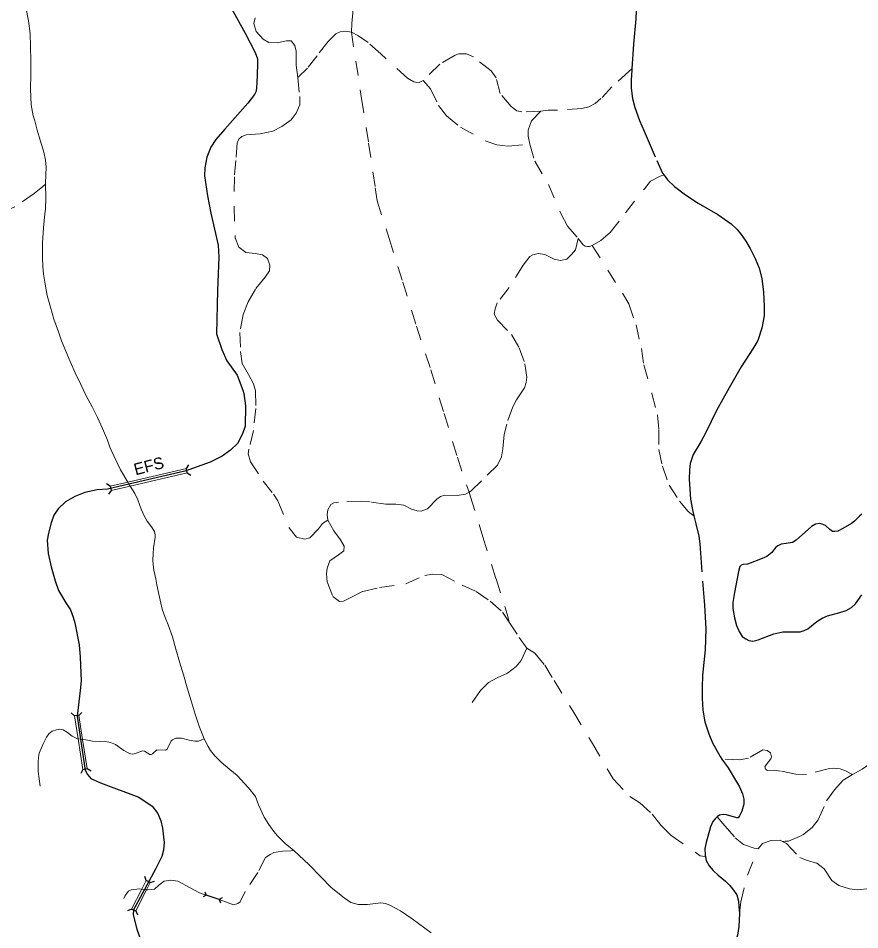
# Model space of a CAD drawing. Extents: x 703.1 to 728.9, y 7316.2 to 7344.3.
# Drawn here: x 708.41 to 714.18, y 7332.5 to 7338.75 of the extents above; entities that cross this region are included whole.
import ezdxf
from ezdxf.enums import TextEntityAlignment as Align

# ---------------------------------------------------------------- set-up
doc = ezdxf.new("R2010")
doc.units = 0
doc.header["$LTSCALE"] = 0.032
for name, pattern in [('DOTTED', [1.5, 0.3, -1.2]), ('LONG_DASHED', [7.5, 6, -1.5]), ('MEDIUM_DASHED', [4.5, 3, -1.5])]:
    doc.linetypes.add(name, pattern=pattern)
for name, color, linetype, lineweight in [('15', 7, 'Continuous', 25), ('29', 7, 'Continuous', 25), ('30', 7, 'Continuous', 13), ('31', 7, 'Continuous', 25), ('4', 7, 'LONG_DASHED', 25), ('5', 7, 'LONG_DASHED', 13), ('6', 7, 'MEDIUM_DASHED', 13), ('7', 7, 'DOTTED', 13)]:
    doc.layers.add(name, color=color, linetype=linetype, lineweight=lineweight)
doc.layers.add('61', color=7, linetype='Continuous')

msp = doc.modelspace()

# ---------------------------------------------------------------- linework, layer by layer
at = {"layer": '15'}
for points in [[(709.8722, 7338.8202), (709.9672, 7338.652), (710.0352, 7338.5185), (710.0515, 7338.4757), (710.0509, 7338.4335), (710.0459, 7338.3088), (710.0421, 7338.2534), (710.0308, 7338.2319), (709.9842, 7338.1715), (709.8274, 7337.9932), (709.7645, 7337.9227), (709.7305, 7337.8698), (709.7034, 7337.8012), (709.6895, 7337.7282), (709.687, 7337.6727), (709.7072, 7337.5355), (709.7317, 7337.4177), (709.7808, 7337.1973), (709.7864, 7337.1148), (709.7763, 7336.8868), (709.7707, 7336.5901), (709.8065, 7336.4825), (709.8418, 7336.4031)], [(709.8418, 7336.4031), (709.911, 7336.3061), (709.9507, 7336.2035), (709.957, 7336.1796), (709.9683, 7336.0952), (709.9658, 7335.9566), (709.9489, 7335.9044)], [(709.9489, 7335.9044), (709.9149, 7335.8364), (709.8658, 7335.7923), (709.8091, 7335.7495), (709.7254, 7335.7086), (709.5793, 7335.6557), (709.5535, 7335.6463), (709.1697, 7335.558)], [(709.1697, 7335.558), (709.0222, 7335.5241), (708.9517, 7335.5191), (708.8674, 7335.5002), (708.7987, 7335.4731), (708.7333, 7335.4378), (708.6842, 7335.3899), (708.654, 7335.3446), (708.6351, 7335.293), (708.6187, 7335.2212), (708.6086, 7335.1733), (708.6156, 7335.082), (708.6357, 7334.9901), (708.6634, 7334.8944), (708.6873, 7334.8289), (708.7371, 7334.7438), (708.7685, 7334.6972), (708.7874, 7334.6469), (708.7988, 7334.6066), (708.8277, 7334.4567), (708.8359, 7334.3716), (708.841, 7334.2092), (708.834, 7334.143), (708.8139, 7333.9667), (708.8377, 7333.8096)], [(708.8377, 7333.8096), (708.8699, 7333.5971), (708.8843, 7333.5662), (708.9082, 7333.5397), (708.9737, 7333.5095), (709.2381, 7333.4125), (709.3287, 7333.3508), (709.3677, 7333.2992), (709.3879, 7333.2501), (709.3986, 7333.199), (709.4111, 7333.1008), (709.4061, 7333.0479), (709.3948, 7333.0038), (709.3545, 7332.922), (709.277, 7332.7781)], [(709.277, 7332.7781), (709.2015, 7332.6379), (709.1977, 7332.6052), (709.2236, 7332.505), (709.2701, 7332.3753), (709.3092, 7332.2997), (709.4206, 7332.1555), (709.4634, 7332.0838), (709.5024, 7331.9943), (709.5188, 7331.9238), (709.5244, 7331.8261), (709.5194, 7331.714), (709.5043, 7331.6183), (709.481, 7331.5233), (709.4457, 7331.4439), (709.3991, 7331.3608), (709.3035, 7331.2512), (709.2575, 7331.1965), (709.1933, 7331.102), (709.1606, 7331.034), (709.1445, 7330.9905)]]:
    msp.add_lwpolyline(points, dxfattribs=at)
at = {"layer": '29'}
for p, q in [((709.5636, 7335.666), (709.5805, 7335.6906)), ((709.5691, 7335.636), (709.5636, 7335.666)), ((709.5691, 7335.636), (709.5939, 7335.6189)), ((709.0406, 7335.5439), (709.0157, 7335.5608)), ((709.0406, 7335.5439), (709.0464, 7335.514)), ((709.0464, 7335.514), (709.0297, 7335.4893)), ((708.7951, 7333.9695), (708.773, 7333.9895)), ((708.8255, 7333.9709), (708.7951, 7333.9695)), ((708.8255, 7333.9709), (708.8458, 7333.9932)), ((708.8541, 7333.6003), (708.8388, 7333.5744)), ((708.8541, 7333.6003), (708.8837, 7333.6079)), ((708.8837, 7333.6079), (708.9093, 7333.5928)), ((709.2884, 7332.84), (709.2788, 7332.8681)), ((709.3158, 7332.8265), (709.2884, 7332.84)), ((709.3158, 7332.8265), (709.3443, 7332.8361)), ((709.1873, 7332.6434), (709.1598, 7332.6314)), ((709.1873, 7332.6434), (709.2158, 7332.6323)), ((709.2158, 7332.6323), (709.2278, 7332.6051))]:
    msp.add_line(p, q, dxfattribs=at)
at = {"layer": '30'}
for points in [[(709.0406, 7335.5439), (709.1611, 7335.572), (709.5636, 7335.666)], [(709.5691, 7335.636), (709.178, 7335.5447), (709.0464, 7335.514)], [(708.7951, 7333.9695), (708.8203, 7333.812), (708.8541, 7333.6003)], [(708.8255, 7333.9709), (708.8516, 7333.8079), (708.8837, 7333.6079)], [(709.2884, 7332.84), (709.258, 7332.781), (709.1873, 7332.6434)], [(709.3158, 7332.8265), (709.2899, 7332.7761), (709.2158, 7332.6323)]]:
    msp.add_lwpolyline(points, dxfattribs=at)
at = {"layer": '31'}
for p, q in [((709.6999, 7332.7399), (709.6775, 7332.7289)), ((709.6889, 7332.7623), (709.6999, 7332.7399)), ((709.7875, 7332.71), (709.6999, 7332.7399)), ((709.8097, 7332.721), (709.7875, 7332.71)), ((709.7875, 7332.71), (709.7983, 7332.6876))]:
    msp.add_line(p, q, dxfattribs=at)
at = {"layer": '4'}
for points in [[(712.7566, 7339.3395), (712.7398, 7339.2266), (712.7211, 7339.1613), (712.697, 7339.0718), (712.6574, 7338.9158), (712.6508, 7338.8663), (712.6451, 7338.7508), (712.6295, 7338.575), (712.6178, 7338.4067)], [(712.6178, 7338.4067), (712.6172, 7338.3979), (712.613, 7338.3301), (712.6137, 7338.2749), (712.6235, 7338.2032), (712.6393, 7338.1422), (712.6707, 7338.0522), (712.7028, 7337.9785), (712.7894, 7337.778), (712.829, 7337.6905), (712.8393, 7337.6771)], [(712.8393, 7337.6771), (712.8632, 7337.6461), (712.9118, 7337.5997), (712.986, 7337.542), (713.0722, 7337.4862), (713.2083, 7337.4087), (713.2994, 7337.344), (713.3374, 7337.3066), (713.3685, 7337.2717), (713.3999, 7337.2242), (713.4291, 7337.174), (713.4644, 7337.1062), (713.4923, 7337.0395), (713.5103, 7336.9679), (713.5202, 7336.8752), (713.5268, 7336.7788), (713.5253, 7336.7122), (713.5091, 7336.6291), (713.4827, 7336.5441), (713.4475, 7336.4864), (713.3679, 7336.3621), (713.2852, 7336.218), (713.1998, 7336.0632), (713.1247, 7335.9135), (713.0914, 7335.8495), (713.0387, 7335.7613), (713.0194, 7335.701), (713.0143, 7335.6572), (713.0124, 7335.5925), (713.0209, 7335.4549), (713.0371, 7335.3698), (713.0444, 7335.3401)], [(714.1948, 7335.3515), (714.1787, 7335.3385), (714.1457, 7335.3049), (714.125, 7335.2881), (714.0643, 7335.2545), (714.0303, 7335.2351), (714.0109, 7335.2325), (713.9954, 7335.2338), (713.976, 7335.2474), (713.9456, 7335.2739), (713.9237, 7335.2849), (713.9082, 7335.2894), (713.8778, 7335.2849), (713.8513, 7335.2674), (713.745, 7335.173), (713.7198, 7335.1588), (713.6758, 7335.151), (713.6416, 7335.1465), (713.6202, 7335.1355), (713.6054, 7335.1252), (713.5782, 7335.0896), (713.5437, 7335.0624), (713.5288, 7335.0547), (713.4777, 7335.0346), (713.4105, 7335.0101), (713.3821, 7335.0075), (713.3672, 7335.0036), (713.3601, 7334.9933), (713.3491, 7334.9584), (713.3217, 7334.8162), (713.3116, 7334.7464), (713.3116, 7334.7056), (713.3226, 7334.641), (713.3372, 7334.588), (713.3546, 7334.5466), (713.376, 7334.513), (713.3999, 7334.4968), (713.4212, 7334.4858), (713.4471, 7334.482), (713.4839, 7334.4897), (713.5912, 7334.5311), (713.6549, 7334.546), (713.7021, 7334.5453), (713.7389, 7334.5447), (713.7725, 7334.546), (713.8003, 7334.5544), (713.8255, 7334.5667), (713.8501, 7334.5861), (713.886, 7334.6165), (713.9242, 7334.6398), (713.9597, 7334.6553), (714.0453, 7334.6786), (714.0886, 7334.6908), (714.1248, 7334.7115), (714.1533, 7334.7368), (714.1953, 7334.8001)], [(713.0444, 7335.3401), (713.0574, 7335.2867), (713.0781, 7335.2011), (713.0857, 7335.1478), (713.1021, 7334.8933), (713.1164, 7334.7289), (713.1256, 7334.5665), (713.1222, 7334.4219), (713.1034, 7334.248), (713.1006, 7334.1618), (713.1012, 7334.0907)], [(713.1012, 7334.0907), (713.106, 7334.0075), (713.1193, 7333.9276), (713.1457, 7333.8463), (713.1717, 7333.7848), (713.2246, 7333.6896), (713.2364, 7333.6725), (713.2785, 7333.6115)], [(713.2785, 7333.6115), (713.3366, 7333.5164), (713.3569, 7333.4815), (713.3772, 7333.4333), (713.387, 7333.3977), (713.387, 7333.3641), (713.3718, 7333.3146), (713.3565, 7333.2835), (713.3483, 7333.2702), (713.3375, 7333.2689), (713.2677, 7333.2905), (713.2455, 7333.293), (713.2202, 7333.2886), (713.2046, 7333.2762)], [(713.2046, 7333.2762), (713.1891, 7333.2638), (713.1729, 7333.2454), (713.1589, 7333.208), (713.1272, 7333.1014), (713.1193, 7333.0596), (713.1212, 7333.0133), (713.1235, 7333.002)], [(713.1235, 7333.002), (713.1288, 7332.9765), (713.1479, 7332.9409), (713.1767, 7332.9073), (713.2097, 7332.8762), (713.2617, 7332.8344), (713.2902, 7332.8058), (713.3086, 7332.7836), (713.3381, 7332.7404), (713.3496, 7332.6979), (713.3527, 7332.6611), (713.3572, 7332.6135)], [(713.3572, 7332.6135), (713.3518, 7332.5254), (713.3422, 7332.4651), (713.3337, 7332.439), (713.3242, 7332.42), (713.307, 7332.3959), (713.2823, 7332.3756), (713.2278, 7332.3388), (713.1995, 7332.3134), (713.1881, 7332.2969), (713.1729, 7332.2658), (713.1589, 7332.2303), (713.1421, 7332.1744), (713.1358, 7332.1376), (713.1358, 7332.0843)]]:
    msp.add_lwpolyline(points, dxfattribs=at)
at = {"layer": '5'}
for points in [[(708.4628, 7338.8291), (708.4814, 7338.7352), (708.4916, 7338.649), (708.4942, 7338.5578), (708.4967, 7338.4666), (708.4972, 7338.3669), (708.4944, 7338.2672), (708.4988, 7338.1594), (708.5124, 7338.0852), (708.5236, 7338.0494), (708.5407, 7337.9852), (708.5537, 7337.9394), (708.5847, 7337.8352), (708.5973, 7337.7801), (708.6007, 7337.7313), (708.5979, 7337.6254), (708.5979, 7337.6156)], [(708.5979, 7337.6156), (708.5984, 7337.5196), (708.5971, 7337.4446), (708.5933, 7337.4131), (708.5838, 7337.3153)], [(708.5838, 7337.3153), (708.5767, 7337.2138), (708.5758, 7337.1114), (708.5798, 7337.0502), (708.5829, 7336.9994), (708.5957, 7336.9297), (708.6086, 7336.8532)], [(708.6086, 7336.8532), (708.6315, 7336.7731), (708.6544, 7336.6908), (708.6854, 7336.6035), (708.7076, 7336.5416), (708.7358, 7336.4705), (708.766, 7336.3993), (708.8016, 7336.3223), (708.8384, 7336.2426), (708.8751, 7336.163), (708.9164, 7336.0896), (708.9531, 7336.0161), (708.9875, 7335.9395), (709.0219, 7335.8594), (709.0378, 7335.8129), (709.0659, 7335.7521), (709.111, 7335.657), (709.1611, 7335.572)], [(709.1611, 7335.572), (709.1643, 7335.5666), (709.1697, 7335.558), (709.178, 7335.5447)], [(709.178, 7335.5447), (709.2101, 7335.4932), (709.2305, 7335.4516), (709.2528, 7335.3866), (709.275, 7335.3359), (709.2946, 7335.3055), (709.3244, 7335.2654), (709.3447, 7335.2335), (709.349, 7335.2096), (709.349, 7335.1946), (709.3388, 7335.1215), (709.3351, 7335.0808), (709.3339, 7335.0365), (709.3345, 7335.0081), (709.3407, 7334.9692), (709.3539, 7334.9081), (709.3608, 7334.8669), (709.3795, 7334.7841), (709.3982, 7334.7014), (709.4173, 7334.6445), (709.4392, 7334.5933), (709.4687, 7334.5118), (709.4908, 7334.4259), (709.5171, 7334.3386), (709.5434, 7334.2498), (709.5697, 7334.1609), (709.5972, 7334.0712), (709.6247, 7333.9815), (709.6522, 7333.8914), (709.6858, 7333.811)], [(708.8203, 7333.812), (708.8128, 7333.8138), (708.7809, 7333.83), (708.7474, 7333.855), (708.718, 7333.8734), (708.6953, 7333.8777), (708.6715, 7333.8723), (708.6438, 7333.865), (708.6196, 7333.8469), (708.6034, 7333.8234), (708.5819, 7333.778), (708.5536, 7333.7137), (708.549, 7333.6864), (708.5468, 7333.649), (708.5468, 7333.5863), (708.5601, 7333.4863)], [(708.8377, 7333.8096), (708.8224, 7333.8115), (708.8203, 7333.812)], [(709.6858, 7333.811), (709.6454, 7333.7953), (709.6216, 7333.7945), (709.5831, 7333.8014), (709.5304, 7333.816), (709.4916, 7333.816), (709.4675, 7333.8045), (709.4598, 7333.7972), (709.431, 7333.7406), (709.4198, 7333.7337), (709.3598, 7333.7364), (709.3306, 7333.7095), (709.3211, 7333.7041), (709.313, 7333.7041), (709.275, 7333.7279), (709.2642, 7333.7287), (709.2046, 7333.7075), (709.1923, 7333.7068), (709.173, 7333.7106), (709.1336, 7333.7326), (709.0771, 7333.7722), (709.0438, 7333.7857), (709.0211, 7333.7911), (708.9195, 7333.795), (708.8732, 7333.8053), (708.8516, 7333.8079), (708.8377, 7333.8096)], [(709.6858, 7333.811), (709.712, 7333.7595), (709.7287, 7333.7315), (709.7583, 7333.6948), (709.8023, 7333.6508), (709.8614, 7333.6004), (709.9125, 7333.5589), (709.9892, 7333.4758), (710.0368, 7333.4151), (710.0576, 7333.3591), (710.0975, 7333.2752), (710.1283, 7333.224), (710.1627, 7333.1769), (710.1874, 7333.1473), (710.2414, 7333.0929), (710.2885, 7333.0554), (710.3002, 7333.0446)], [(710.3002, 7333.0446), (710.4056, 7332.9474), (710.4855, 7332.8651), (710.5574, 7332.7924), (710.6449, 7332.7213), (710.6913, 7332.6885), (710.7424, 7332.6741), (710.8047, 7332.6749), (710.8966, 7332.6869), (710.9282, 7332.6821), (710.9578, 7332.6701), (711.0313, 7332.6317), (711.112, 7332.5758), (711.2414, 7332.4815)]]:
    msp.add_lwpolyline(points, dxfattribs=at)
at = {"layer": '6'}
for points in [[(710.6951, 7338.6573), (710.6989, 7338.7173), (710.7165, 7338.9628)], [(710.0349, 7338.7563), (710.0261, 7338.7178), (710.0426, 7338.6638), (710.0899, 7338.6099), (710.1295, 7338.5878), (710.1867, 7338.5845), (710.2506, 7338.6), (710.2819, 7338.5983), (710.3072, 7338.5675), (710.3171, 7338.5278), (710.316, 7338.4331), (710.327, 7338.3473)], [(710.6951, 7338.6573), (710.6517, 7338.6655), (710.6186, 7338.66), (710.5878, 7338.6467), (710.5361, 7338.595), (710.4602, 7338.497), (710.3931, 7338.4111), (710.327, 7338.3473)], [(711.1875, 7338.3279), (711.1544, 7338.311), (711.1236, 7338.3187), (711.0807, 7338.3419), (710.8958, 7338.5092), (710.8089, 7338.5885), (710.7402, 7338.6352), (710.6951, 7338.6573)], [(711.994, 7338.1168), (711.8635, 7338.1112), (711.8298, 7338.1187), (711.7911, 7338.1474), (711.7162, 7338.2374), (711.6881, 7338.3454), (711.6532, 7338.3941), (711.5321, 7338.489), (711.4846, 7338.5103), (711.4309, 7338.5103), (711.406, 7338.5015), (711.3011, 7338.4378), (711.1875, 7338.3279)], [(712.6178, 7338.4067), (712.5978, 7338.3886), (712.4822, 7338.2842), (712.406, 7338.203), (712.3673, 7338.1693), (712.3236, 7338.1468), (712.2762, 7338.1355), (712.1089, 7338.123), (712.044, 7338.123), (711.994, 7338.1168)], [(710.327, 7338.3473), (710.3407, 7338.2168), (710.3407, 7338.1595), (710.3165, 7338.1023), (710.2813, 7338.0571), (710.2191, 7338.0115), (710.1552, 7337.9795), (710.0683, 7337.9619), (709.9726, 7337.9542), (709.944, 7337.9421), (709.9231, 7337.9245), (709.9121, 7337.9003), (709.9032, 7337.7791), (709.8928, 7337.6652), (709.8906, 7337.4626), (709.8988, 7337.2474), (709.9241, 7337.1835), (709.972, 7337.1467), (710.0369, 7337.1412), (710.0843, 7337.1313), (710.1206, 7337.1059), (710.1349, 7337.0608), (710.1327, 7337.0223), (710.1041, 7336.9771), (710.0364, 7336.8962), (709.9869, 7336.8092), (709.9527, 7336.7223), (709.9291, 7336.5973), (709.9346, 7336.4685), (709.9461, 7336.3864), (709.9901, 7336.3094), (710.0226, 7336.2473), (710.0385, 7336.1982), (710.0391, 7336.0776), (710.0237, 7335.9268), (709.9923, 7335.7974), (709.9879, 7335.7655), (710.0033, 7335.7115), (710.0907, 7335.5789), (710.1612, 7335.4886), (710.1914, 7335.444), (710.2651, 7335.2601), (710.3196, 7335.1956), (710.3768, 7335.1802), (710.4099, 7335.189), (710.4693, 7335.2529), (710.4979, 7335.2892), (710.5332, 7335.3115)], [(711.1875, 7338.3279), (711.2381, 7338.2699), (711.2917, 7338.1562), (711.3479, 7338.0838), (711.4422, 7338.0057), (711.6132, 7337.9133), (711.6918, 7337.8845), (711.7692, 7337.877), (711.9191, 7337.8907)], [(711.994, 7338.1168), (711.9304, 7338.0493), (711.9079, 7337.9856), (711.9079, 7337.9457), (711.9191, 7337.8907)], [(711.9191, 7337.8907), (711.9533, 7337.7728), (712.0457, 7337.6141), (712.1337, 7337.4099), (712.1774, 7337.3287), (712.2513, 7337.243)], [(712.347, 7337.1953), (712.406, 7337.2284), (712.4696, 7337.2838), (712.5758, 7337.4195), (712.7043, 7337.5847), (712.7456, 7337.6354), (712.8116, 7337.6708), (712.8193, 7337.6726), (712.8393, 7337.6771)], [(708.5979, 7337.6156), (708.5779, 7337.5991), (708.52, 7337.5512), (708.3879, 7337.4614), (708.2371, 7337.3978), (707.9965, 7337.3046), (707.7775, 7337.1983), (707.65, 7337.1208), (707.628, 7337.1021), (707.6077, 7337.0716)], [(712.2513, 7337.243), (712.2317, 7337.1657), (712.2055, 7337.1333), (712.1718, 7337.102), (712.1293, 7337.092), (712.0856, 7337.1008), (712.022, 7337.1333), (711.9758, 7337.1395), (711.9396, 7337.132), (711.9196, 7337.1195), (711.8722, 7337.0608), (711.7779, 7336.9066), (711.6956, 7336.8017), (711.6806, 7336.7617), (711.675, 7336.7248), (711.6962, 7336.6824), (711.7936, 7336.5837), (711.846, 7336.4925), (711.8853, 7336.3844), (711.8978, 7336.292), (711.8928, 7336.2557), (711.8816, 7336.2183), (711.8279, 7336.1358), (711.8011, 7336.089), (711.7599, 7335.9691), (711.7424, 7335.8979), (711.7336, 7335.8005), (711.7255, 7335.7449), (711.698, 7335.6887), (711.5869, 7335.58), (711.517, 7335.5125), (711.5021, 7335.5034)], [(712.2513, 7337.243), (712.2837, 7337.2004), (712.2974, 7337.1914), (712.3135, 7337.1887), (712.3269, 7337.189), (712.347, 7337.1953)], [(711.5021, 7335.5034), (711.4783, 7335.4888), (711.4209, 7335.4801), (711.336, 7335.4838), (711.3054, 7335.4732), (711.2804, 7335.4557), (711.218, 7335.3895), (711.1743, 7335.3721), (711.1456, 7335.3746), (711.1069, 7335.387), (711.0557, 7335.4133), (711.0008, 7335.4208), (710.9309, 7335.422), (710.8235, 7335.437), (710.763, 7335.4414), (710.6069, 7335.4352), (710.5744, 7335.4302), (710.5545, 7335.4189), (710.5332, 7335.3827), (710.5283, 7335.349), (710.5332, 7335.3115)], [(710.5332, 7335.3115), (710.5741, 7335.2375), (710.6205, 7335.1764), (710.6465, 7335.1323), (710.6442, 7335.1017), (710.6069, 7335.0734), (710.5481, 7335.0327), (710.53, 7334.9829), (710.5232, 7334.9433), (710.53, 7334.8879), (710.5685, 7334.7872), (710.6126, 7334.7544), (710.6408, 7334.7567), (710.6827, 7334.777), (710.7742, 7334.8223), (710.8885, 7334.8494), (711.0682, 7334.8743), (711.1988, 7334.9326), (711.2509, 7334.9405), (711.3142, 7334.9394), (711.4555, 7334.8658), (711.55, 7334.8222), (711.6461, 7334.7566), (711.732, 7334.6808), (711.7764, 7334.6126)], [(711.7764, 7334.6126), (711.8457, 7334.506), (711.8982, 7334.4342)], [(711.8982, 7334.4342), (711.8598, 7334.3482), (711.8259, 7334.3075), (711.7659, 7334.2622), (711.6958, 7334.2305), (711.6359, 7334.1977), (711.5811, 7334.1428), (711.4929, 7334.0206)], [(711.8982, 7334.4342), (711.952, 7334.3985), (712.021, 7334.3171), (712.0854, 7334.2107), (712.2206, 7333.9929), (712.3489, 7333.7785), (712.4908, 7333.537), (712.6055, 7333.4165), (712.6722, 7333.3724), (712.7582, 7333.2955), (712.8198, 7333.218), (712.8887, 7333.149), (713.0866, 7333.0098), (713.1035, 7333.0062), (713.1235, 7333.002)], [(713.4856, 7333.0575), (713.5151, 7333.0944), (713.5739, 7333.115), (713.6357, 7333.1164), (713.651, 7333.108)], [(713.651, 7333.108), (713.6784, 7333.0929), (713.7697, 7332.9987), (713.8197, 7332.9766), (713.8874, 7332.9589), (713.9374, 7332.9191), (713.9889, 7332.8396), (714.0375, 7332.8058), (714.1111, 7332.7837), (714.1626, 7332.7749), (714.2523, 7332.7852), (714.2847, 7332.8028), (714.3264, 7332.8204)], [(710.3002, 7333.0446), (710.2802, 7333.0438), (710.2219, 7333.0415), (710.1634, 7333.0316), (710.1376, 7333.0177), (710.1069, 7332.9969), (710.0534, 7332.8957), (709.9672, 7332.7648), (709.9315, 7332.6934), (709.9151, 7332.682), (709.8864, 7332.6721), (709.8326, 7332.6942), (709.7875, 7332.71)], [(713.3572, 7332.6135), (713.3664, 7332.6924), (713.4106, 7332.8764), (713.4856, 7333.0575)], [(709.2899, 7332.7761), (709.2991, 7332.7747), (709.3437, 7332.7807), (709.3755, 7332.8084), (709.4102, 7332.8352), (709.4557, 7332.8431), (709.5058, 7332.8357), (709.59, 7332.7901), (709.6495, 7332.7564), (709.6657, 7332.751), (709.6999, 7332.7399), (709.7875, 7332.71)], [(709.1336, 7332.7172), (709.1445, 7332.738), (709.1663, 7332.7658), (709.1842, 7332.7747), (709.2407, 7332.7836), (709.258, 7332.781), (709.277, 7332.7781), (709.2899, 7332.7761)]]:
    msp.add_lwpolyline(points, dxfattribs=at)
at = {"layer": '7'}
for points in [[(710.6951, 7338.6573), (710.7652, 7338.2031), (710.8133, 7337.8972), (710.859, 7337.5913), (710.8727, 7337.5004), (710.9534, 7337.2426), (711.0478, 7336.9426), (711.141, 7336.6426), (711.2401, 7336.3426), (711.3309, 7336.0426), (711.4217, 7335.7426), (711.5021, 7335.5034)], [(712.347, 7337.1953), (712.5533, 7336.8686), (712.5967, 7336.7943), (712.6472, 7336.6499), (712.6843, 7336.4879), (712.6997, 7336.3771), (712.7565, 7336.1801), (712.7943, 7336.0343), (712.8035, 7335.9313), (712.8035, 7335.7953), (712.8287, 7335.6817), (712.8742, 7335.5506), (712.9443, 7335.4413), (713.0045, 7335.3698), (713.0243, 7335.355), (713.0444, 7335.3401)], [(711.5021, 7335.5034), (711.5125, 7335.4723), (711.5974, 7335.1973), (711.687, 7334.9092), (711.7636, 7334.6663), (711.7716, 7334.6326), (711.7764, 7334.6126)], [(714.1308, 7333.5675), (714.1971, 7333.6044), (714.4533, 7333.779), (714.5117, 7333.804), (714.5902, 7333.85), (714.6521, 7333.9032), (714.6925, 7333.9516), (714.7509, 7334.0282), (714.7667, 7334.0647), (714.7699, 7334.1695), (714.7734, 7334.2104), (714.7885, 7334.2564), (714.8424, 7334.3604), (714.8992, 7334.4457), (714.9908, 7334.5548), (715.0824, 7334.6687), (715.1669, 7334.8067)], [(714.1308, 7333.5675), (714.0837, 7333.5925), (714.0464, 7333.6068), (714.0004, 7333.6092), (713.973, 7333.6072), (713.8152, 7333.5659), (713.743, 7333.5683), (713.6375, 7333.5906), (713.5962, 7333.5977), (713.5486, 7333.5937), (713.5343, 7333.6032), (713.5296, 7333.6183), (713.5399, 7333.6342), (713.5708, 7333.6739), (713.5756, 7333.689), (713.57, 7333.7159), (713.5462, 7333.7326), (713.5169, 7333.735), (713.4189, 7333.6783), (713.3594, 7333.6679), (713.2364, 7333.6725)], [(713.651, 7333.108), (713.671, 7333.1089), (713.6918, 7333.1099), (713.7894, 7333.1504), (713.854, 7333.2032), (713.896, 7333.2564), (713.9528, 7333.3854), (714.0079, 7333.4628), (714.0674, 7333.5287), (714.1308, 7333.5675)], [(713.2046, 7333.2762), (713.2563, 7333.2139), (713.3277, 7333.1321), (713.3832, 7333.0861), (713.4562, 7333.0615), (713.4856, 7333.0575)]]:
    msp.add_lwpolyline(points, dxfattribs=at)

# ---------------------------------------------------------------- texts
at = {"layer": '61'}
msp.add_text('EFS', height=0.08, rotation=14.501, dxfattribs=at).set_placement((709.3158, 7335.6446), align=Align.CENTER)

doc.saveas('drawing.dxf')
